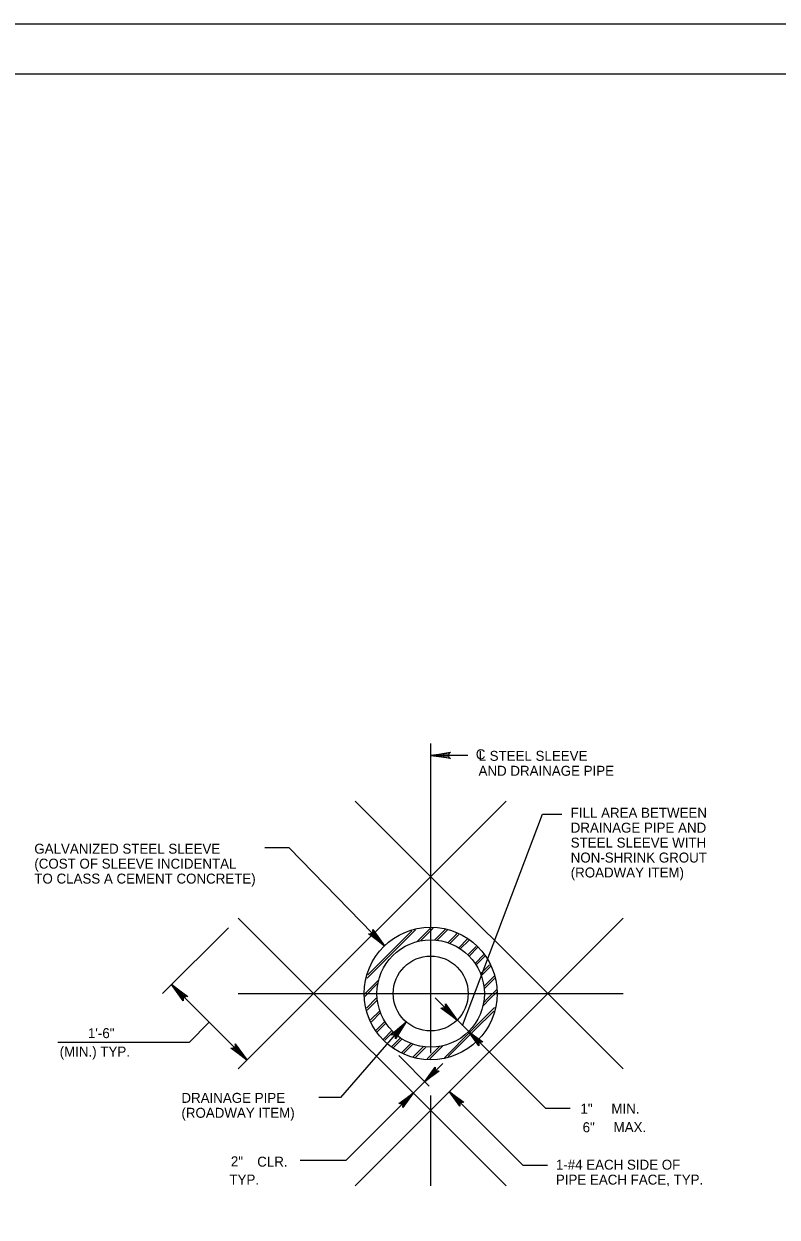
# Model space of a CAD drawing. Extents: x 235 to 2276, y 116 to 1308.
# Drawn here: x 1742 to 1968.8, y 944.9 to 1304.4 of the extents above; entities that cross this region are included whole.
import ezdxf

# ---------------------------------------------------------------- set-up
doc = ezdxf.new("R2010")
doc.units = 0
doc.layers.add('1', color=7, linetype='Continuous')
doc.layers.add('PLT-BNDY', color=7, linetype='Continuous')

msp = doc.modelspace()

# ---------------------------------------------------------------- linework, layer by layer
at = {"layer": '1'}
for p, q in [((1460.42, 1289.41), (2246.42, 1289.41)), ((1864.46, 994.28), (1864.46, 1087.57)), ((1875.65, 1084.02), (1864.46, 1084.02)), ((1806.49, 989.58), (1887.17, 1070.26)), ((1922.42, 989.58), (1841.74, 1070.26)), ((1874.04, 1002.71), (1898.09, 1066.31)), ((1898.09, 1066.31), (1903.99, 1066.31)), ((1821.85, 1056.16), (1814.55, 1056.16)), ((1821.85, 1056.16), (1850.53, 1026.63)), ((1783.77, 1012.3), (1803.58, 1032.1)), ((1806.49, 1035.02), (1887.17, 954.33)), ((1841.74, 954.33), (1922.42, 1035.02)), ((1862.89, 1030.46), (1864.44, 1032.01)), ((1863.29, 1030.06), (1865.21, 1031.98)), ((1867.29, 1030.06), (1868.95, 1031.72)), ((1848.08, 1020.46), (1857.68, 1030.06)), ((1848.88, 1020.46), (1858.48, 1030.06)), ((1857.68, 1030.06), (1858.77, 1031.16)), ((1858.48, 1030.06), (1859.93, 1031.51)), ((1860.31, 1027.9), (1862.48, 1030.06)), ((1861.36, 1028.15), (1862.88, 1029.66)), ((1862.48, 1030.06), (1862.88, 1030.46)), ((1863.29, 1030.06), (1862.88, 1029.65)), ((1865.63, 1028.4), (1867.29, 1030.06)), ((1868.09, 1030.06), (1866.37, 1028.34)), ((1868.09, 1030.06), (1869.52, 1031.49)), ((1869.63, 1027.6), (1872.09, 1030.06)), ((1870.21, 1027.38), (1872.89, 1030.06)), ((1872.09, 1030.06), (1872.38, 1030.34)), ((1872.89, 1030.06), (1872.95, 1030.12)), ((1872.89, 1026.06), (1875.58, 1028.75)), ((1873.38, 1025.75), (1876, 1028.37)), ((1875.61, 1023.98), (1878.13, 1026.5)), ((1876.01, 1023.58), (1878.56, 1026.13)), ((1877.81, 1021.38), (1880.46, 1024.03)), ((1878.12, 1020.89), (1880.75, 1023.52)), ((1881.69, 1020.46), (1882.18, 1020.95)), ((1845.29, 1016.88), (1848.88, 1020.46)), ((1845.57, 1017.96), (1848.08, 1020.46)), ((1879.47, 1018.24), (1881.69, 1020.46)), ((1879.69, 1017.66), (1882.47, 1020.44)), ((1880.46, 1014.43), (1883.55, 1017.52)), ((1786.46, 1014.98), (1809.17, 992.26)), ((1844.5, 1012.09), (1848.85, 1016.44)), ((1844.62, 1011.41), (1848.6, 1015.39)), ((1880.55, 1013.72), (1883.66, 1016.83)), ((1806.49, 1012.3), (1922.42, 1012.3)), ((1845.21, 1007.99), (1848.08, 1010.86)), ((1845.32, 1007.31), (1848.41, 1010.4)), ((1848.08, 1010.86), (1848.35, 1011.14)), ((1899.14, 977.61), (1865.78, 1010.97)), ((1880.16, 1008.53), (1882.49, 1010.86)), ((1880.33, 1009.5), (1881.69, 1010.86)), ((1881.69, 1010.86), (1884.25, 1013.42)), ((1882.49, 1010.86), (1884.37, 1012.74)), ((1846.34, 1004.33), (1849.15, 1007.13)), ((1846.63, 1003.81), (1849.37, 1006.55)), ((1876.89, 1001.26), (1883.71, 1008.08)), ((1877.69, 1001.26), (1883.44, 1007)), ((1791.76, 997.57), (1797.81, 1003.62)), ((1857.05, 1003.77), (1837.27, 980.99)), ((1848.08, 1001.26), (1850.68, 1003.87)), ((1848.88, 1001.26), (1851, 1003.38)), ((1848.06, 1001.25), (1848.08, 1001.26)), ((1848.35, 1000.74), (1848.88, 1001.26)), ((1850.21, 998.59), (1852.77, 1001.15)), ((1850.63, 998.22), (1853.17, 1000.75)), ((1868.58, 992.95), (1876.89, 1001.26)), ((1869.74, 993.31), (1877.69, 1001.26)), ((1791.76, 997.57), (1752.25, 997.57)), ((1852.76, 996.35), (1855.36, 998.95)), ((1853.19, 995.97), (1855.85, 998.64)), ((1855.77, 994.55), (1858.5, 997.29)), ((1856.34, 994.33), (1859.08, 997.07)), ((1859.2, 993.18), (1862.3, 996.29)), ((1859.77, 992.95), (1862.88, 996.06)), ((1863.04, 996.2), (1862.89, 996.06)), ((1863.45, 992.62), (1867.22, 996.39)), ((1864.22, 992.59), (1868.22, 996.59)), ((1864.05, 984.43), (1854.86, 993.63)), ((1859.2, 982.3), (1867.23, 990.33)), ((1867.23, 990.33), (1868.15, 991.26)), ((1838.93, 962.03), (1859.2, 982.3)), ((1864.46, 954.33), (1864.46, 981.58)), ((1892.3, 960.5), (1870.1, 982.7)), ((1837.27, 980.99), (1830.78, 980.99)), ((1906.44, 977.61), (1899.14, 977.61)), ((1838.93, 962.03), (1825.12, 962.03)), ((1899.6, 960.5), (1892.3, 960.5))]:
    msp.add_line(p, q, dxfattribs=at)
for points in [[(1870.13, 1083.31), (1869.92, 1083.72), (1864.46, 1084.02), (1870.13, 1083.31), (1870.42, 1083.06), (1864.46, 1084.02), (1869.92, 1084.29), (1870.11, 1084.7), (1864.46, 1084.02), (1870.42, 1084.97), (1870.11, 1084.7)], [(1847.08, 1031.2), (1846.94, 1030.76), (1850.53, 1026.63), (1847.08, 1031.2), (1847.06, 1031.58), (1850.53, 1026.63), (1846.53, 1030.36), (1846.1, 1030.22), (1850.53, 1026.63), (1845.69, 1030.25), (1846.1, 1030.22)], [(1789.96, 1010.46), (1790.11, 1010.9), (1786.46, 1014.98), (1789.96, 1010.46), (1789.99, 1010.08), (1786.46, 1014.98), (1790.51, 1011.31), (1790.94, 1011.46), (1786.46, 1014.98), (1791.34, 1011.43), (1790.94, 1011.46)], [(1868.93, 1008.83), (1868.79, 1008.39), (1872.44, 1004.31), (1868.93, 1008.83), (1868.9, 1009.21), (1872.44, 1004.31), (1868.39, 1007.98), (1867.96, 1007.84), (1872.44, 1004.31), (1867.55, 1007.86), (1867.96, 1007.84)], [(1852.79, 999.95), (1853.24, 999.84), (1857.05, 1003.77), (1852.79, 999.95), (1852.42, 999.9), (1857.05, 1003.77), (1853.68, 999.47), (1853.85, 999.06), (1857.05, 1003.77), (1853.86, 998.65), (1853.85, 999.06)], [(1878.97, 996.89), (1879.1, 997.28), (1875.89, 1000.87), (1878.97, 996.89), (1879, 996.55), (1875.89, 1000.87), (1879.45, 997.64), (1879.83, 997.76), (1875.89, 1000.87), (1880.19, 997.74), (1879.83, 997.76)], [(1805.67, 996.78), (1805.52, 996.34), (1809.17, 992.26), (1805.67, 996.78), (1805.64, 997.16), (1809.17, 992.26), (1805.12, 995.93), (1804.69, 995.78), (1809.17, 992.26), (1804.29, 995.81), (1804.69, 995.78)], [(1866.67, 988.88), (1866.28, 989.01), (1862.69, 985.79), (1866.67, 988.88), (1867, 988.91), (1862.69, 985.79), (1865.92, 989.36), (1865.79, 989.74), (1862.69, 985.79), (1865.81, 990.1), (1865.79, 989.74)], [(1855.23, 979.22), (1855.62, 979.09), (1859.2, 982.3), (1855.23, 979.22), (1854.89, 979.19), (1859.2, 982.3), (1855.97, 978.74), (1856.1, 978.36), (1859.2, 982.3), (1856.08, 978), (1856.1, 978.36)], [(1873.19, 978.72), (1873.32, 979.11), (1870.1, 982.7), (1873.19, 978.72), (1873.22, 978.39), (1870.1, 982.7), (1873.67, 979.47), (1874.05, 979.6), (1870.1, 982.7), (1874.41, 979.58), (1874.05, 979.6)]]:
    msp.add_lwpolyline(points, dxfattribs=at)
for radius in [19.99, 16.17, 11.29]:
    msp.add_circle((1864.46, 1012.3), radius, dxfattribs=at)
at = {"layer": 'PLT-BNDY'}
msp.add_lwpolyline([(1420.42, 1304.41), (2261.42, 1304.41), (2261.42, 710.41), (1420.42, 710.41)], close=True, dxfattribs=at)

# ---------------------------------------------------------------- texts
at = {"layer": '1'}
for s, height, p in [('C', 3, (1878.04, 1082.87)), ('L STEEL SLEEVE', 3, (1878.87, 1082.4)), ('AND DRAINAGE PIPE', 3, (1878.87, 1077.9)), ('FILL AREA BETWEEN', 3, (1906.62, 1065.26)), ('DRAINAGE PIPE AND', 3, (1906.62, 1060.76)), ('GALVANIZED STEEL SLEEVE', 3, (1745.13, 1054.42)), ('STEEL SLEEVE WITH', 3, (1906.62, 1056.26)), ('NON-SHRINK GROUT', 3, (1906.62, 1051.76)), ('(COST OF SLEEVE INCIDENTAL', 3, (1745.13, 1049.92)), ('(ROADWAY ITEM)', 3, (1906.62, 1047.26)), ('TO CLASS A CEMENT CONCRETE)', 3, (1745.13, 1045.42)), ('1\'-6"', 3.003, (1761.27, 998.85)), ('(MIN.) TYP.', 3, (1752.76, 993.31)), ('DRAINAGE PIPE', 3, (1789.42, 979.36)), ('(ROADWAY ITEM)', 3, (1789.42, 974.86)), ('1"', 3.003, (1909.54, 976.1)), ('MIN.', 3, (1918.87, 976.14)), ('6"', 3.003, (1910.21, 970.51)), ('MAX.', 3, (1919.53, 970.55)), ('2"', 3.003, (1804.3, 960.23)), ('CLR.', 3, (1812.24, 960.14)), ('1-#4 EACH SIDE OF', 3, (1902.16, 959.23)), ('TYP.', 3, (1803.87, 954.75)), ('PIPE EACH FACE, TYP.', 3, (1902.16, 954.73))]:
    msp.add_text(s, height=height, dxfattribs=at).set_placement(p)

doc.saveas('drawing.dxf')
